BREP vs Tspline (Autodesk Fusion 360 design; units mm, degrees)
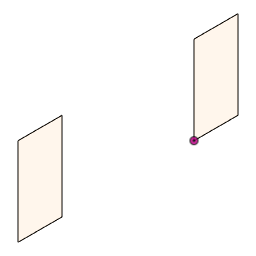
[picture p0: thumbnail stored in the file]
sketch "Sketch1" plane through (0, 0, 0) normal (1, 0, 0) x axis (0, 1, 0)
  line L1 (0, 100) -> (0, 0)
  line L2 (50, 100) -> (0, 100)
  line L3 (50, 0) -> (50, 100)
  line L4 (0, 0) -> (50, 0)
  line L5 (-150, 100) -> (-200, 100)
  line L6 (-150, 0) -> (-150, 100)
  line L7 (-200, 0) -> (-150, 0)
  line L8 (-200, 100) -> (-200, 0)
  point P1 (0, 0)
  point P2 (0, 0)
  point P6 (0, 0)
  point P9 (-200, 0)
  point P10 (-200, 0)
  point P3 (0, 100)
  point P4 (50, 100)
  point P11 (-200, 100)
  point P8 (-150, 100)
  point P7 (-150, 0)
  coincident P1 P2
  vertical L1
  perpendicular L1 L2
  perpendicular L2 L3
  coincident P1 P6
  perpendicular L1 L4
  vertical L8
  perpendicular L5 L8
  perpendicular L5 L6
  perpendicular L7 L8
  coincident P9 P10
  collinear L4 L7
  dimension "d1" distance P2 P3 = 100
  dimension "d2" distance P3 P4 = 50
  dimension "d3" distance P10 P11 = 100
  dimension "d4" distance P8 P11 = 50
  dimension "d5" distance P1 P7 = 150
